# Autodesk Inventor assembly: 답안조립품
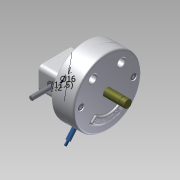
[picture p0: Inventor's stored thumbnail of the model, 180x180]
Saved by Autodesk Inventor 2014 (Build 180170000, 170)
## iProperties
Created: 2015-04
Part Number: 답안조립품
Document SubType Name: Assembly
Designer: Administrator
Author: Administrator
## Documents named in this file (15)
- C:\Documents and Settings\Administrator\바탕 화면\350406V1032\답안조립품.iam
- C:\Documents and Settings\Administrator\바탕 화면\350406V1032\본체.ipt
- C:\Documents and Settings\Administrator\바탕 화면\350406V1032\가변스프링.ipt
- C:\Documents and Settings\Administrator\바탕 화면\350406V1032\베어링62_22.ipt
- C:\Documents and Settings\Administrator\바탕 화면\350406V1032\멈춤링.ipt
- C:\Documents and Settings\Administrator\바탕 화면\350406V1032\커버.ipt
- C:\Documents and Settings\Administrator\바탕 화면\350406V1032\축.ipt
- C:\Documents and Settings\Administrator\바탕 화면\350406V1032\커버2.ipt
- C:\Documents and Settings\Administrator\바탕 화면\350406V1032\M 5 x 12.ipt
- C:\Documents and Settings\Administrator\바탕 화면\350406V1032\M 10 x 35.ipt
- C:\Documents and Settings\Administrator\바탕 화면\350406V1032\슬라이더3.ipt
- C:\Documents and Settings\Administrator\바탕 화면\350406V1032\부시.ipt
- C:\Documents and Settings\Administrator\바탕 화면\350406V1032\슬라이더.ipt
- C:\Documents and Settings\Administrator\바탕 화면\350406V1032\슬라이더2.ipt
- C:\Documents and Settings\Administrator\바탕 화면\350406V1032\평행핀.ipt
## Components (6 placed, 4 different names)
1. 가변스프링:1
2. M 5 x 12:1
3. M 5 x 12:2
4. M 10 x 35:1
5. M 10 x 35:2
6. KS B 1320 B B 5 x  20:1 — 플러쉬:1
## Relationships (1: Flush 1)
- 플러쉬:1 [Flush]: KS B 1320 B B 5 x  20:1
